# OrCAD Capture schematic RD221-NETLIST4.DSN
size A3
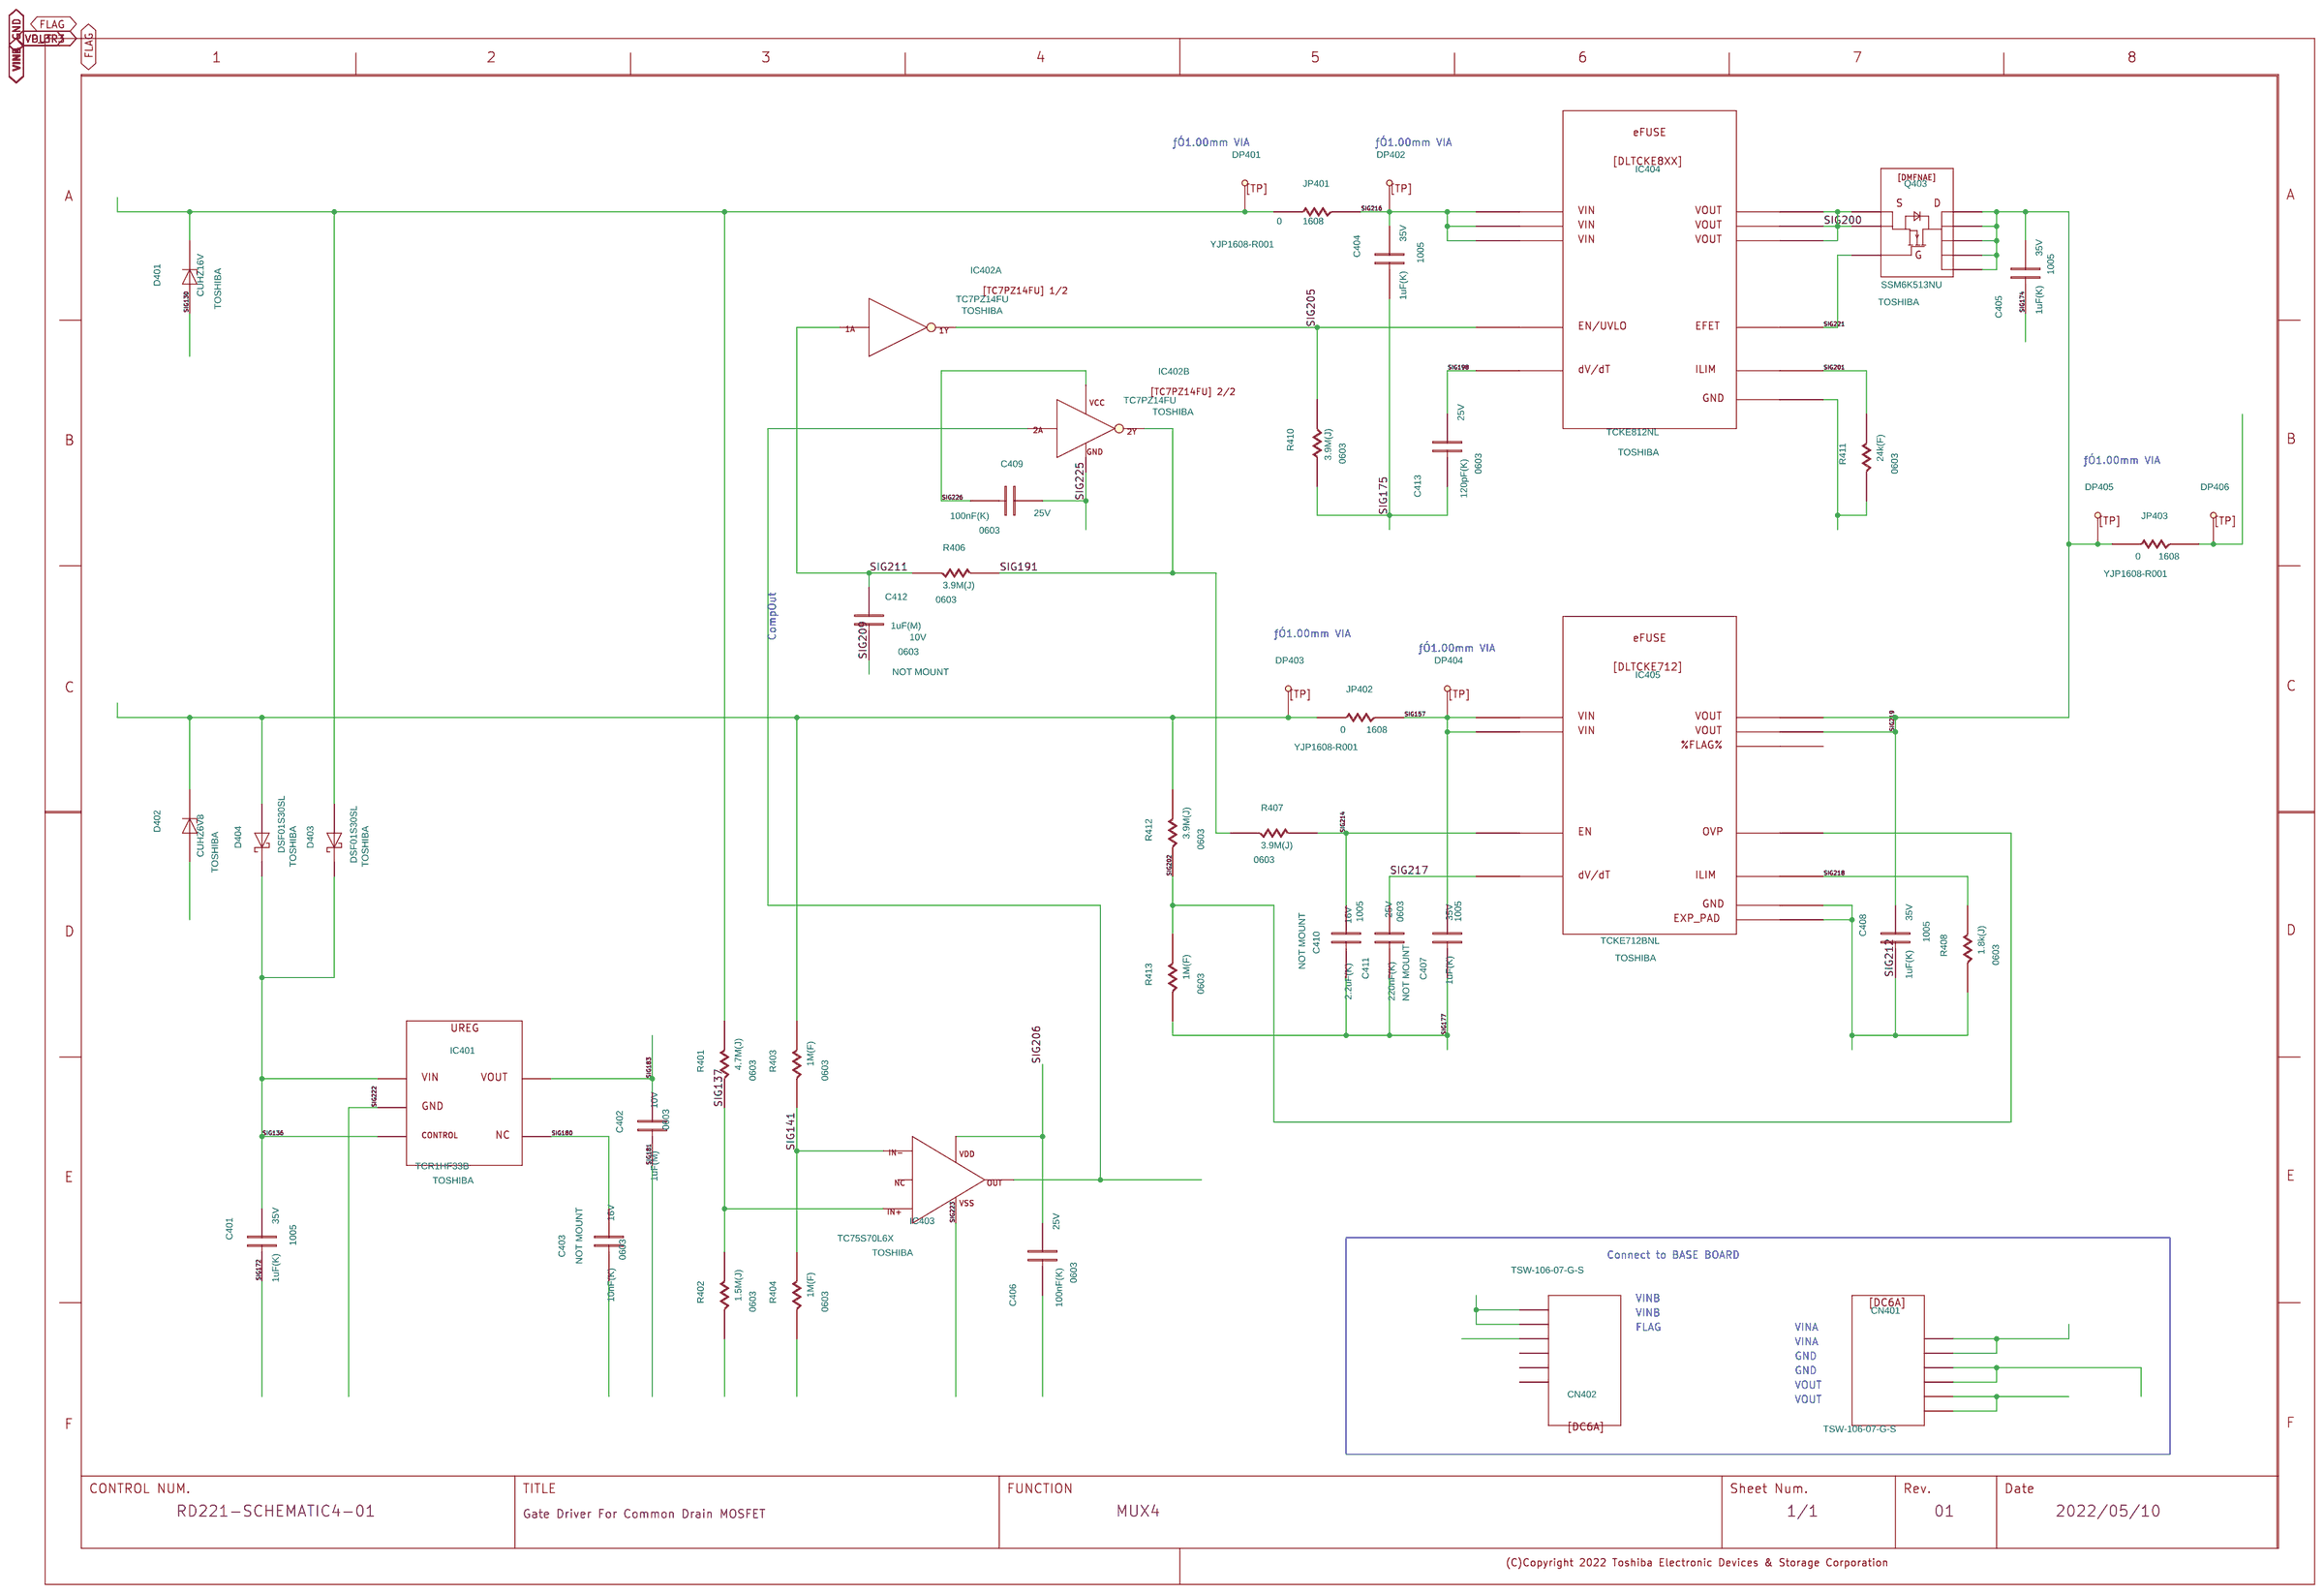
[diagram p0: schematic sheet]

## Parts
C401  DC
C402  DC
C403  DC
C404  DC
C405  DC
C406  DC
C407  DC
C408  DC
C409  DC
C410  DC
C411  DC
C412  DC
C413  DC
CN401  DC6A
CN402  DC6A
D401  DZD
D402  DZD
D403  DSBD
D404  DSBD
DP401  DTP
DP402  DTP
DP403  DTP
DP404  DTP
DP405  DTP
DP406  DTP
IC401  DL1HFXX
IC402  TC7PZ14FU_1  (sections A,B)
IC403  TC75S70L6X
IC404  DLTCKE8XX
IC405  DLTCKE712
JP401  DR
JP402  DR
JP403  DR
Q403  DMFNAE
R401  DR
R402  DR
R403  DR
R404  DR
R406  DR
R407  DR
R408  DR
R410  DR
R411  DR
R412  DR
R413  DR
U?#1  WAKU_DEF100

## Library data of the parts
C401 C405 C407 C408 = DC: COMP: DP0000016125; COMPONENTNAME: DP0000016125_package; FUNCN: DP0000016125; GCOUNT: 1; MAXGCOUNT: 1; OUMEPARTTYPE: C; SIZECODESMD: 1005; VAL1: 1uF(K); VAL2: 35V; VAL3: GRM155R6YA105KE11D
C402 = DC: COMP: DP0007093000; COMPONENTNAME: DP0007093000_package; FUNCN: DP0007093000; GCOUNT: 1; MAXGCOUNT: 1; OUMEPARTTYPE: C; REUSEDCOMP: C203; REUSEDFILE: RDxxx-SCHEMATIC3-01_REV_1_00_20211111; SIZECODESMD: 0603; VAL1: 1uF(M); VAL2: 10V; VAL3: GRM033R61A105ME15D
C403 = DC: COMP: DP0010383000; COMPONENTNAME: DP0010383000_package; FUNCN: DP0010383000; GCOUNT: 1; MAXGCOUNT: 1; NOTMOUNT: NOT MOUNT; OUMEPARTTYPE: C; REUSEDCOMP: C202; REUSEDFILE: RDxxx-SCHEMATIC3-01_REV_1_00_20211111; SIZECODESMD: 0603; VAL1: 10nF(K); VAL2: 16V; VAL3: GRM033R71C103KE14D
C404 = DC: COMP: DP0000016125; COMPONENTNAME: DP0000016125_package; FUNCN: DP0000016125; GCOUNT: 1; MAXGCOUNT: 1; OUMEPARTTYPE: C; REUSEDCOMP: C207; REUSEDFILE: RDxxx-SCHEMATIC3-01_REV_1_00_20211111; SIZECODESMD: 1005; VAL1: 1uF(K); VAL2: 35V; VAL3: GRM155R6YA105KE11D
C406 = DC: COMP: DP0000015403; COMPONENTNAME: DP0000015403_package; FUNCN: DP0000015403; GCOUNT: 1; MAXGCOUNT: 1; OUMEPARTTYPE: C; SIZECODESMD: 0603; VAL1: 100nF(K); VAL2: 25V; VAL3: GRM033R61E104KE14D
C409 = DC: COMP: DP0000015403; COMPONENTNAME: DP0000015403_package; FUNCN: DP0000015403; GCOUNT: 1; MAXGCOUNT: 1; OUMEPARTTYPE: C; REUSEDCOMP: C209; REUSEDFILE: RDxxx-SCHEMATIC3-01_REV_1_00_20211111; SIZECODESMD: 0603; VAL1: 100nF(K); VAL2: 25V; VAL3: GRM033R61E104KE14D
C410 = DC: COMP: DP0000016132; COMPONENTNAME: DP0000016132_package; FUNCN: DP0000016132; GCOUNT: 1; MAXGCOUNT: 1; NOTMOUNT: NOT MOUNT; OUMEPARTTYPE: C; SIZECODESMD: 1005; VAL1: 2.2uF(K); VAL2: 16V; VAL3: GRM155R61C225KE11D
C411 = DC: COMP: DP0010594000; COMPONENTNAME: DP0010594000_package; FUNCN: DP0010594000; GCOUNT: 1; MAXGCOUNT: 1; NOTMOUNT: NOT MOUNT; OUMEPARTTYPE: C; SIZECODESMD: 0603; VAL1: 220nF(K); VAL2: 25V; VAL3: GRM033R61E224KE
C412 = DC: COMP: DP0007093000; COMPONENTNAME: DP0007093000_package; FUNCN: DP0007093000; GCOUNT: 1; MAXGCOUNT: 1; NOTMOUNT: NOT MOUNT; OUMEPARTTYPE: C; SIZECODESMD: 0603; VAL1: 1uF(M); VAL2: 10V; VAL3: GRM033R61A105ME15D
C413 = DC: COMP: DP0000015102; COMPONENTNAME: DP0000015102; FUNCN: DP0000015102; GCOUNT: 1; MAXGCOUNT: 1; OUMEPARTTYPE: C; SIZECODESMD: 0603; VAL1: 120pF(K); VAL2: 25V; VAL3: GRM033B11E121KA01D
CN401 CN402 = DC6A: COMP: DP0010563000; COMPONENTNAME: DP0010563000_package; FUNCN: DP0010563000; GCOUNT: 1; MAXGCOUNT: 1; OUMEPARTTYPE: CN; VAL3: TSW-106-07-G-S
D401 = DZD: COMP: DP0010580000; COMPONENTNAME: DP0010580000_package; FUNCN: DP0010580000; GCOUNT: 1; MAXGCOUNT: 1; OUMEPARTTYPE: D; USERCOMPTEXT3: TOSHIBA; VAL1: CUHZ16V; VAL3: CUHZ16V
D402 = DZD: COMP: DP0010558000; COMPONENTNAME: DP0010558000_package; FUNCN: DP0010558000; GCOUNT: 1; MAXGCOUNT: 1; OUMEPARTTYPE: D; USERCOMPTEXT3: TOSHIBA; VAL1: CUHZ6V8; VAL3: CUHZ6V8
D403 D404 = DSBD: COMP: DP0010560000; COMPONENTNAME: DP0010560000_package; FUNCN: DP0010560000; GCOUNT: 1; MAXGCOUNT: 1; OUMEPARTTYPE: D; USERCOMPTEXT3: TOSHIBA; VAL1: DSF01S30SL; VAL3: DSF01S30SL
DP401 DP403 DP405 = DTP: COMP: DP9000817000; COMPONENTNAME: DP9000817000_package; FUNCN: DP9000817000; GCOUNT: 1; MAXGCOUNT: 1; NOTMOUNT: NOT MOUNT; OUMEPARTTYPE: TP; REUSEDCOMP: DP301; REUSEDFILE: RDxxx-SCHEMATIC4-01_REV_1_00_20211111
DP402 DP404 DP406 = DTP: COMP: DP9000817000; COMPONENTNAME: DP9000817000_package; FUNCN: DP9000817000; GCOUNT: 1; MAXGCOUNT: 1; NOTMOUNT: NOT MOUNT; OUMEPARTTYPE: TP; REUSEDCOMP: DP302; REUSEDFILE: RDxxx-SCHEMATIC4-01_REV_1_00_20211111
IC401 = DL1HFXX: COMP: DP0008120000; COMPONENTNAME: DP0008120000_package; FUNCN: DP0008120000; SAVEAREA0: -37394,-7797,68343,35643; SAVECOUNT: 26; UPDATEDATE: 2021/11/24; UPDATETIME: 10:48:25; UPDATEUSER: w90028dm; USERCOMPTEXT3: TOSHIBA; VAL1: TCR1HF33B; VAL3: TCR1HF33B
IC402 = TC7PZ14FU_1: COMP: DP0010588000; CaptureCellPackProp: TC7PZ14FU_1A; FUNCN: DP0010588000_1; USERCOMPTEXT3: TOSHIBA; VAL1: TC7PZ14FU; VAL3: TC7PZ14FU; COMPONENTNAME: DP0010588000
IC403 = TC75S70L6X: COMP: DP0010561000; COMPONENTNAME: DP0010561000; FUNCN: DP0010561000; USERCOMPTEXT3: TOSHIBA
IC404 = DLTCKE8XX: COMP: DP0010586000; COMPONENTNAME: DP0010586000_package; FUNCN: DP0010586000; GCOUNT: 1; MAXGCOUNT: 1; OUMEPARTTYPE: IC; USERCOMPTEXT3: TOSHIBA; VAL1: TCKE812NL; VAL3: TCKE812NL
IC405 = DLTCKE712: COMP: DP0010587000; COMPONENTNAME: DP0010587000_package; FUNCN: DP0010587000; GCOUNT: 1; MAXGCOUNT: 1; OUMEPARTTYPE: IC; SAVEAREA0: -71139,-11050,83572,74593; UPDATEDATE: 2021/11/11; UPDATETIME: 07:02:47; UPDATEUSER: t5459927; USERCOMPTEXT3: TOSHIBA; VAL1: TCKE712BNL; VAL3: TCKE712BNL
JP401 = DR: COMP: DP0001376000; COMPCOMMENT: 0; COMPONENTNAME: DP0001376000_package; FUNCN: DP0001376000; GCOUNT: 1; MAXGCOUNT: 1; OUMEPARTTYPE: R; REUSEDCOMP: JP202; REUSEDFILE: RDxxx-SCHEMATIC3-01_REV_1_00_20211111; SIZECODESMD: 1608; VAL1: 200u(X); VAL2: 30mW; VAL3: YJP1608-R001
JP402 JP403 = DR: COMP: DP0001376000; COMPCOMMENT: 0; COMPONENTNAME: DP0001376000_package; FUNCN: DP0001376000; GCOUNT: 1; MAXGCOUNT: 1; OUMEPARTTYPE: R; SIZECODESMD: 1608; VAL1: 200u(X); VAL2: 30mW; VAL3: YJP1608-R001
Q403 = DMFNAE: COMP: DP0010595000; COMPONENTNAME: DP0010595000_package; FUNCN: DP0010595000; GCOUNT: 1; MAXGCOUNT: 1; OUMEPARTTYPE: Q; USERCOMPTEXT3: TOSHIBA; VAL1: SSM6K513NU; VAL3: SSM6K513NU
R401 = DR: ADSMODELNAME: s_ERJ1GNF1004C; CDMASTERCADCELG: KC0054; COMP: DP0000151160; COMPONENTNAME: DP0000151160; FNLEADFREETHET1GT2GMCTH1: N_N_N; FUNCN: DP0000151160; GCOUNT: 1; MAXGCOUNT: 1; MOUNTINGFORMSMD: SMD; NOMINALRESISTAN: 1M; OUMECLASSIFICATION: ÅèïRí; OUMEMAKER: NAE pi\jbNGNgjbNfoCX; OUMEMAKERKATAMEI: ERJ1GNF1004C; OUMEPARTTYPE: R; POWERRATING: 50m; RESISTANCETOLER: F; SIZECODESMD: 0603; VAL1: 4.7M(J); VAL2: 50mW; VAL3: ERJ1GNJ475C
R402 = DR: ADSMODELNAME: s_ERJ1GNF1004C; CDMASTERCADCELG: KC0054; COMP: DP0000151148; COMPONENTNAME: DP0000151148; FNLEADFREETHET1GT2GMCTH1: N_N_N; FUNCN: DP0000151148; GCOUNT: 1; MAXGCOUNT: 1; MOUNTINGFORMSMD: SMD; NOMINALRESISTAN: 1M; OUMECLASSIFICATION: ÅèïRí; OUMEMAKER: NAE pi\jbNGNgjbNfoCX; OUMEMAKERKATAMEI: ERJ1GNF1004C; OUMEPARTTYPE: R; POWERRATING: 50m; RESISTANCETOLER: F; SIZECODESMD: 0603; VAL1: 1.5M(J); VAL2: 50mW; VAL3: ERJ1GNJ155C
R403 R404 R413 = DR: ADSMODELNAME: s_ERJ1GNF1004C; CDMASTERCADCELG: KC0054; COMP: DP0000152120; COMPONENTNAME: DP0000152120_package; FNLEADFREETHET1GT2GMCTH1: N_N_N; FUNCN: DP0000152120; GCOUNT: 1; MAXGCOUNT: 1; MOUNTINGFORMSMD: SMD; NOMINALRESISTAN: 1M; OUMECLASSIFICATION: ÅèïRí; OUMEMAKER: NAE pi\jbNGNgjbNfoCX; OUMEMAKERKATAMEI: ERJ1GNF1004C; OUMEPARTTYPE: R; POWERRATING: 50m; RESISTANCETOLER: F; SIZECODESMD: 0603; VAL1: 1M(F); VAL2: 50mW; VAL3: ERJ1GNF1004C
R406 R407 R410 R412 = DR: ADSMODELNAME: s_ERJ1GNF1004C; CDMASTERCADCELG: KC0054; COMP: DP0000151158; COMPONENTNAME: DP0000151158; FNLEADFREETHET1GT2GMCTH1: N_N_N; FUNCN: DP0000151158; GCOUNT: 1; MAXGCOUNT: 1; MOUNTINGFORMSMD: SMD; NOMINALRESISTAN: 1M; OUMECLASSIFICATION: ÅèïRí; OUMEMAKER: NAE pi\jbNGNgjbNfoCX; OUMEMAKERKATAMEI: ERJ1GNF1004C; OUMEPARTTYPE: R; POWERRATING: 50m; RESISTANCETOLER: F; SIZECODESMD: 0603; VAL1: 3.9M(J); VAL2: 50mW; VAL3: ERJ1GNJ395C
R408 = DR: ADSMODELNAME: s_ERJ1GNF1004C; CDMASTERCADCELG: KC0054; COMP: DP0000151078; COMPONENTNAME: DP0000151078; FNLEADFREETHET1GT2GMCTH1: N_N_N; FUNCN: DP0000151078; GCOUNT: 1; MAXGCOUNT: 1; MOUNTINGFORMSMD: SMD; NOMINALRESISTAN: 1M; OUMECLASSIFICATION: ÅèïRí; OUMEMAKER: NAE pi\jbNGNgjbNfoCX; OUMEMAKERKATAMEI: ERJ1GNF1004C; OUMEPARTTYPE: R; POWERRATING: 50m; RESISTANCETOLER: F; SIZECODESMD: 0603; VAL1: 1.8k(J); VAL2: 50mW; VAL3: ERJ1GNJ182C
R411 = DR: ADSMODELNAME: s_ERJ1GNF1004C; CDMASTERCADCELG: KC0054; COMP: DP0000152081; COMPONENTNAME: DP0000152081; FNLEADFREETHET1GT2GMCTH1: N_N_N; FUNCN: DP0000152081; GCOUNT: 1; MAXGCOUNT: 1; MOUNTINGFORMSMD: SMD; NOMINALRESISTAN: 1M; OUMECLASSIFICATION: ÅèïRí; OUMEMAKER: NAE pi\jbNGNgjbNfoCX; OUMEMAKERKATAMEI: ERJ1GNF1004C; OUMEPARTTYPE: R; POWERRATING: 50m; RESISTANCETOLER: F; SIZECODESMD: 0603; VAL1: 24k(F); VAL2: 50mW; VAL3: ERJ1GNF2402C
U?#1 = WAKU_DEF100: DATE: 2022/05/10; DRAWINGNUMBER: RD221-SCHEMATIC4-01; FUNCTION: MUX4; PLOTDATE: 2021/11/11; REVISION: 01; SAVEAREA0: 148187,-66180,486823,89919; SAVECOUNT: 6; SHEETNUMBER: 1/1; TITLE: Gate Driver For Common Drain MOSFET; UPDATEDATE: 2022/05/10; UPDATETIME: 17:01:50

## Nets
GND: C401.2 C402.2 C403.2 C404.2 C405.2 C406.2 C407.2 C408.2 C409.1 C410.2 C411.2 C412.2 C413.2 CN401.3 CN401.4 D401.A D402.A IC401.2 IC402.2 IC403.2 IC404.11 IC405.6 IC405.11 R402.2 R404.2 R408.2 R410.1 R411.2 R413.2
VINA: CN401.1 CN401.2 D401.C D403.A DP401.1 JP401.1 R401.1
VINB: CN402.5 CN402.6 D402.C D404.A DP403.1 JP402.1 R403.1 R412.1
FLAG: CN402.4 IC402.3 IC403.1
SIG136: C401.1 D403.C D404.C IC401.1 IC401.3
SIG137: IC403.3 R401.2 R402.1
SIG141: IC403.4 R403.2 R404.1
SIG157: C407.1 DP404.1 IC405.1 IC405.2 JP402.2
SIG180: C403.1 IC401.4
SIG191: IC402.4 R406.1 R407.2
SIG198: C413.1 IC404.1
SIG200: IC404.6 IC404.7 IC404.8 Q403.4 Q403.8
SIG201: IC404.10 R411.1
SIG202: IC405.7 R412.2 R413.1
SIG205: IC402.6 IC404.2 R410.2
SIG211: C412.1 IC402.1 R406.2
SIG214: C410.1 IC405.4 R407.1
SIG216: C404.1 DP402.1 IC404.3 IC404.4 IC404.5 JP401.2
SIG217: C411.1 IC405.3
SIG218: IC405.5 R408.1
SIG219: C405.1 C408.1 DP405.1 IC405.9 IC405.10 JP403.1 Q403.1 Q403.2 Q403.5 Q403.6 Q403.7
SIG221: IC404.9 Q403.3
VOUT: CN401.5 CN401.6 DP406.1 JP403.2
VP_3R3: C402.1 C406.1 C409.2 IC401.5 IC402.5 IC403.6

Not connected (* = marked no-connect by the designer): CN402 1 2 3; IC403 5; IC405 8

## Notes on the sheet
- ƒÓ1.00mm VIA
- ƒÓ1.00mm VIA
- ƒÓ1.00mm VIA
- ƒÓ1.00mm VIA
- CompOut
- ƒÓ1.00mm VIA
- Connect to BASE BOARD
- VINB
- VINB
- FLAG
- VINA
- VINA
- GND
- GND
- VOUT
- VOUT
